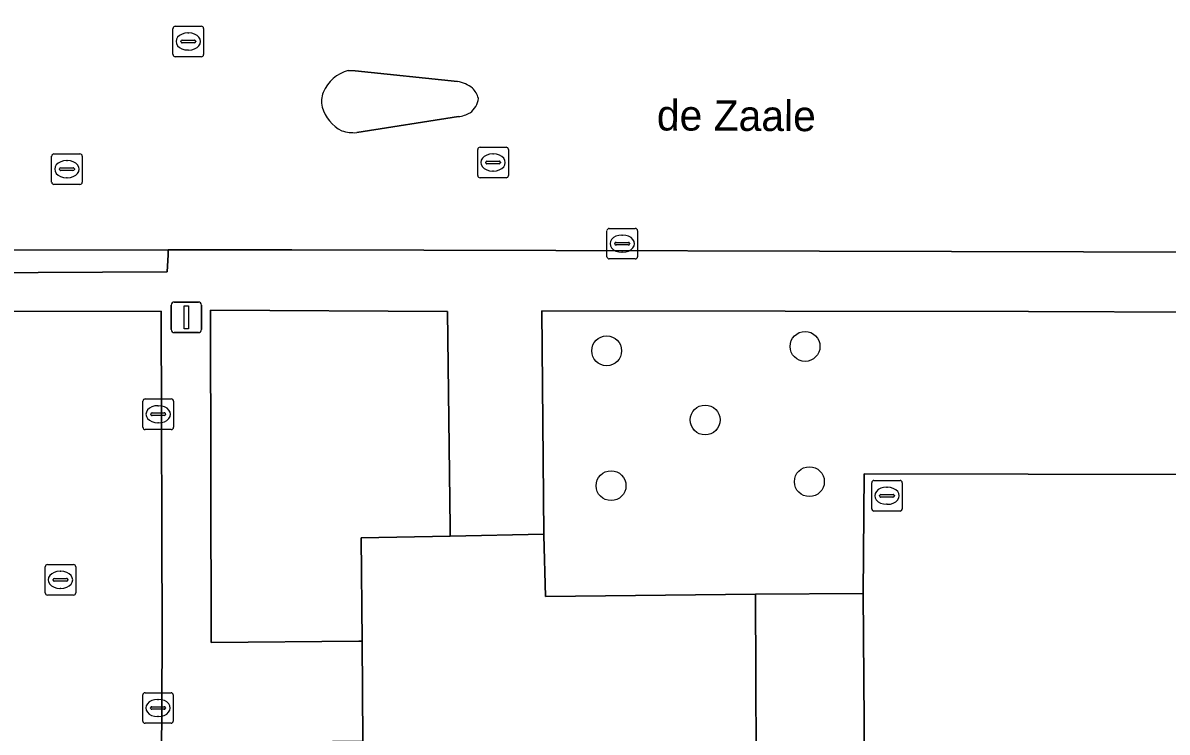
# Model space of a CAD drawing. Extents: x 161477 to 163040, y 383680 to 384871.
# Drawn here: x 161809.61 to 161847.07, y 384356.35 to 384379.58 of the extents above; entities that cross this region are included whole.
import ezdxf

# ---------------------------------------------------------------- set-up
doc = ezdxf.new("R2010")
doc.units = 0
for name, color, linetype in [('IMGEO_Boom', 7, 'Continuous'), ('IMGEO_Groenvoorziening', 7, 'Continuous'), ('IMGEO_Kolk', 7, 'Continuous'), ('IMGEO_Lichtmast', 7, 'Continuous'), ('IMGEO_Openbare_ruimte_label', 7, 'Continuous'), ('IMGEO_Rijbaan_lokaal_open', 7, 'Continuous'), ('IMGEO_Rioolput', 7, 'Continuous'), ('IMGEO_Verkeerseiland_open', 7, 'Continuous'), ('IMGEO_Voetpad_op_trap', 7, 'Continuous'), ('IMGEO_Voetpad_open', 7, 'Continuous')]:
    doc.layers.add(name, color=color, linetype=linetype)

msp = doc.modelspace()

# ---------------------------------------------------------------- linework, layer by layer
at = {"layer": 'IMGEO_Boom'}
for centre in [(161835.213, 384368.986), (161828.719, 384368.843), (161831.942, 384366.577), (161835.355, 384364.556), (161828.862, 384364.424)]:
    msp.add_circle(centre, 0.489, dxfattribs=at)
at = {"layer": 'IMGEO_Groenvoorziening'}
for points in [[(161823.509, 384370.128), (161815.746, 384370.177), (161815.772, 384359.283), (161820.602, 384359.329), (161820.711, 384359.33), (161820.686, 384362.714), (161823.595, 384362.772), (161823.592, 384363.058)], [(161860.901, 384369.01), (161859.337, 384369.912), (161859.393, 384370.069), (161842.531, 384370.13), (161826.596, 384370.149), (161826.665, 384362.833), (161826.665, 384362.807), (161826.719, 384360.791), (161833.591, 384360.874), (161837.12, 384360.892), (161837.147, 384364.815), (161847.882, 384364.794), (161866.104, 384364.813), (161866.116, 384365.577), (161866.118, 384365.909)]]:
    msp.add_lwpolyline(points, close=True, dxfattribs=at)
at = {"layer": 'IMGEO_Kolk'}
for p, q in [((161828.804, 384372.851), (161829.656, 384372.851)), ((161828.729, 384371.925), (161828.729, 384372.777)), ((161829.217, 384372.631), (161829.242, 384372.631)), ((161829.73, 384372.777), (161829.73, 384371.925)), ((161828.988, 384372.345), (161828.988, 384372.357)), ((161829.426, 384372.308), (161829.028, 384372.308)), ((161829.031, 384372.394), (161829.429, 384372.394)), ((161829.472, 384372.357), (161829.472, 384372.345)), ((161829.656, 384371.851), (161828.804, 384371.851)), ((161829.24, 384372.071), (161829.215, 384372.071)), ((161813.613, 384367.264), (161814.465, 384367.264)), ((161813.538, 384366.338), (161813.538, 384367.19)), ((161814.026, 384367.044), (161814.051, 384367.044)), ((161814.539, 384367.19), (161814.539, 384366.338)), ((161813.797, 384366.758), (161813.797, 384366.77)), ((161814.235, 384366.721), (161813.837, 384366.721)), ((161813.84, 384366.807), (161814.238, 384366.807)), ((161814.049, 384366.484), (161814.024, 384366.484)), ((161814.281, 384366.77), (161814.281, 384366.758)), ((161814.465, 384366.264), (161813.613, 384366.264)), ((161837.47, 384364.595), (161838.322, 384364.595)), ((161837.395, 384363.669), (161837.395, 384364.521)), ((161837.883, 384364.375), (161837.908, 384364.375)), ((161838.396, 384364.521), (161838.396, 384363.669)), ((161837.654, 384364.089), (161837.654, 384364.101)), ((161838.092, 384364.052), (161837.694, 384364.052)), ((161837.697, 384364.138), (161838.095, 384364.138)), ((161838.138, 384364.101), (161838.138, 384364.089)), ((161838.322, 384363.595), (161837.47, 384363.595)), ((161837.906, 384363.815), (161837.881, 384363.815)), ((161813.531, 384356.717), (161813.531, 384357.569)), ((161813.606, 384357.643), (161814.458, 384357.643)), ((161814.532, 384357.569), (161814.532, 384356.717)), ((161813.79, 384357.137), (161813.79, 384357.149)), ((161814.228, 384357.1), (161813.83, 384357.1)), ((161813.833, 384357.186), (161814.231, 384357.186)), ((161814.019, 384357.423), (161814.044, 384357.423)), ((161814.274, 384357.149), (161814.274, 384357.137)), ((161814.042, 384356.863), (161814.017, 384356.863)), ((161814.458, 384356.643), (161813.606, 384356.643))]:
    msp.add_line(p, q, dxfattribs=at)
for points in [[(161828.804, 384372.851), (161829.656, 384372.851)], [(161828.729, 384371.925), (161828.729, 384372.777)], [(161829.73, 384372.777), (161829.73, 384371.925)], [(161829.656, 384371.851), (161828.804, 384371.851)], [(161813.613, 384367.264), (161814.465, 384367.264)], [(161813.538, 384366.338), (161813.538, 384367.19)], [(161814.539, 384367.19), (161814.539, 384366.338)], [(161814.465, 384366.264), (161813.613, 384366.264)], [(161837.47, 384364.595), (161838.322, 384364.595)], [(161837.395, 384363.669), (161837.395, 384364.521)], [(161838.396, 384364.521), (161838.396, 384363.669)], [(161838.322, 384363.595), (161837.47, 384363.595)], [(161813.531, 384356.717), (161813.531, 384357.569)], [(161813.606, 384357.643), (161814.458, 384357.643)], [(161814.532, 384357.569), (161814.532, 384356.717)], [(161814.458, 384356.643), (161813.606, 384356.643)]]:
    msp.add_lwpolyline(points, dxfattribs=at)
for centre, radius, start, end in [((161828.806, 384372.775), 0.0765, 91.552, 178.448), ((161828.806, 384372.775), 0.0765, 91.552, 178.448), ((161829.654, 384372.775), 0.0765, 1.552, 88.448), ((161829.654, 384372.775), 0.0765, 1.552, 88.448), ((161829.028, 384372.354), 0.0403, 85.8775, 175.7526), ((161829.025, 384372.344), 0.0366, 178.938, 274.7102), ((161829.429, 384372.351), 0.043, 264.8664, 352.4533), ((161829.433, 384372.356), 0.0386, 1.7309, 96.639), ((161828.806, 384371.927), 0.0765, 181.552, 268.448), ((161828.806, 384371.927), 0.0765, 181.552, 268.448), ((161829.654, 384371.927), 0.0765, 271.552, 358.448), ((161829.654, 384371.927), 0.0765, 271.552, 358.448), ((161813.615, 384367.188), 0.0765, 91.552, 178.448), ((161813.615, 384367.188), 0.0765, 91.552, 178.448), ((161814.463, 384367.188), 0.0765, 1.552, 88.448), ((161814.463, 384367.188), 0.0765, 1.552, 88.448), ((161813.837, 384366.767), 0.0403, 85.8775, 175.7526), ((161813.834, 384366.757), 0.0366, 178.938, 274.7102), ((161814.238, 384366.764), 0.043, 264.8664, 352.4533), ((161814.242, 384366.769), 0.0386, 1.7309, 96.639), ((161813.615, 384366.34), 0.0765, 181.552, 268.448), ((161813.615, 384366.34), 0.0765, 181.552, 268.448), ((161814.463, 384366.34), 0.0765, 271.552, 358.448), ((161814.463, 384366.34), 0.0765, 271.552, 358.448), ((161837.472, 384364.519), 0.0765, 91.552, 178.448), ((161837.472, 384364.519), 0.0765, 91.552, 178.448), ((161838.32, 384364.519), 0.0765, 1.552, 88.448), ((161838.32, 384364.519), 0.0765, 1.552, 88.448), ((161837.694, 384364.098), 0.0403, 85.8775, 175.7526), ((161837.691, 384364.088), 0.0366, 178.938, 274.7102), ((161838.095, 384364.095), 0.043, 264.8664, 352.4533), ((161838.099, 384364.1), 0.0386, 1.7309, 96.639), ((161837.472, 384363.671), 0.0765, 181.552, 268.448), ((161837.472, 384363.671), 0.0765, 181.552, 268.448), ((161838.32, 384363.671), 0.0765, 271.552, 358.448), ((161838.32, 384363.671), 0.0765, 271.552, 358.448), ((161813.608, 384357.567), 0.0765, 91.552, 178.448), ((161813.608, 384357.567), 0.0765, 91.552, 178.448), ((161814.456, 384357.567), 0.0765, 1.552, 88.448), ((161814.456, 384357.567), 0.0765, 1.552, 88.448), ((161813.83, 384357.146), 0.0403, 85.8775, 175.7526), ((161813.827, 384357.136), 0.0366, 178.938, 274.7102), ((161814.231, 384357.143), 0.043, 264.8664, 352.4533), ((161814.235, 384357.148), 0.0386, 1.7309, 96.639), ((161813.608, 384356.719), 0.0765, 181.552, 268.448), ((161813.608, 384356.719), 0.0765, 181.552, 268.448), ((161814.456, 384356.719), 0.0765, 271.552, 358.448), ((161814.456, 384356.719), 0.0765, 271.552, 358.448)]:
    msp.add_arc(centre, radius, start, end, dxfattribs=at)
for centre, major_axis, ratio, start_param, end_param in [((161829.216, 384372.351), (-0.387, 0.002), 0.722429, 4.712389, 7.853982), ((161829.241, 384372.351), (-0.39, 0.002), 0.717154, 1.570796, 4.712389), ((161814.025, 384366.764), (-0.387, 0.002), 0.722429, 4.712389, 7.853982), ((161814.05, 384366.764), (-0.39, 0.002), 0.717154, 1.570796, 4.712389), ((161837.882, 384364.095), (-0.387, 0.002), 0.722429, 4.712389, 7.853982), ((161837.907, 384364.095), (-0.39, 0.002), 0.717154, 1.570796, 4.712389), ((161814.018, 384357.143), (-0.387, 0.002), 0.722429, 4.712389, 7.853982), ((161814.043, 384357.143), (-0.39, 0.002), 0.717154, 1.570796, 4.712389)]:
    msp.add_ellipse(centre, major_axis=major_axis, ratio=ratio, start_param=start_param, end_param=end_param, dxfattribs=at)
at = {"layer": 'IMGEO_Lichtmast'}
for p, q in [((161814.464, 384369.539), (161814.464, 384370.339)), ((161814.464, 384370.339), (161814.464, 384369.539)), ((161814.564, 384370.439), (161815.354, 384370.439)), ((161815.354, 384370.439), (161814.564, 384370.439)), ((161815.454, 384370.339), (161815.454, 384369.539)), ((161815.454, 384369.539), (161815.454, 384370.339)), ((161815.354, 384369.439), (161814.564, 384369.439)), ((161814.564, 384369.439), (161815.354, 384369.439))]:
    msp.add_line(p, q, dxfattribs=at)
msp.add_lwpolyline([(161814.884, 384370.314), (161815.034, 384370.314), (161815.034, 384369.564), (161814.884, 384369.564), (161814.884, 384370.314)], dxfattribs=at)
for centre, start, end in [((161814.564, 384370.339), 90, 180), ((161814.564, 384370.339), 90, 180), ((161815.354, 384370.339), 0, 90), ((161815.354, 384370.339), 360, 90), ((161814.564, 384369.539), 180, 270), ((161814.564, 384369.539), 180, 270), ((161815.354, 384369.539), 270, 0), ((161815.354, 384369.539), 270, 0)]:
    msp.add_arc(centre, 0.1, start, end, dxfattribs=at)
at = {"layer": 'IMGEO_Rijbaan_lokaal_open'}
for points in [[(161807.986, 384389.164), (161807.967, 384386.159), (161807.953, 384382.43), (161807.983, 384372.238), (161807.983, 384372.135), (161814.368, 384372.145), (161818.41, 384372.152), (161844.332, 384372.085), (161861.126, 384372.071), (161865.791, 384372.068), (161865.845, 384382.002), (161864.089, 384382.01), (161859.71, 384382.026), (161858.115, 384382.027), (161834.388, 384382.049), (161828.143, 384382.055), (161827.142, 384382.092)], [(161820.257, 384378.027), (161820.487, 384378.015), (161823.835, 384377.663)], [(161823.868, 384376.515), (161820.537, 384375.987)], [(161814.06, 384323.352), (161814.035, 384329.719), (161814.102, 384340.861), (161814.121, 384351.376), (161814.162, 384359.441), (161814.131, 384370.138), (161807.989, 384370.133), (161807.949, 384361.27), (161807.917, 384350.655), (161807.908, 384348.04), (161807.911, 384343.752), (161807.912, 384342.77), (161807.864, 384334.408), (161807.877, 384324.354)]]:
    msp.add_lwpolyline(points, dxfattribs=at)
for centre, radius, start, end in [((161820.613, 384376.806), 1.272, 106.2566, 156.888), ((161823.687, 384376.676), 0.998, 50.3941, 81.4633), ((161823.804, 384376.919), 0.739, 14.8896, 45.3685), ((161820.099, 384377.02), 0.716, 156.4919, 195.6095), ((161823.868, 384377.17), 0.653, 305.2923, 354.6184), ((161820.613, 384377.16), 1.249, 195.4874, 243.0755), ((161823.753, 384377.513), 1.005, 276.5601, 299.3038), ((161820.48, 384377.543), 1.557, 253.9011, 272.1085)]:
    msp.add_arc(centre, radius, start, end, dxfattribs=at)
at = {"layer": 'IMGEO_Rioolput'}
for p, q in [((161814.522, 384378.548), (161814.522, 384379.4)), ((161814.597, 384379.474), (161815.449, 384379.474)), ((161815.01, 384379.254), (161815.035, 384379.254)), ((161815.523, 384379.4), (161815.523, 384378.548)), ((161814.781, 384378.968), (161814.781, 384378.98)), ((161815.219, 384378.931), (161814.821, 384378.931)), ((161814.824, 384379.017), (161815.222, 384379.017)), ((161815.265, 384378.98), (161815.265, 384378.968)), ((161815.449, 384378.474), (161814.597, 384378.474)), ((161815.033, 384378.694), (161815.008, 384378.694)), ((161824.574, 384375.51), (161825.426, 384375.51)), ((161810.55, 384374.365), (161810.55, 384375.217)), ((161810.625, 384375.291), (161811.477, 384375.291)), ((161811.551, 384375.217), (161811.551, 384374.365)), ((161824.499, 384374.584), (161824.499, 384375.436)), ((161824.987, 384375.29), (161825.012, 384375.29)), ((161825.5, 384375.436), (161825.5, 384374.584)), ((161810.809, 384374.785), (161810.809, 384374.797)), ((161811.247, 384374.748), (161810.849, 384374.748)), ((161810.852, 384374.834), (161811.25, 384374.834)), ((161811.038, 384375.071), (161811.063, 384375.071)), ((161811.293, 384374.797), (161811.293, 384374.785)), ((161824.758, 384375.004), (161824.758, 384375.016)), ((161825.196, 384374.967), (161824.798, 384374.967)), ((161824.801, 384375.053), (161825.199, 384375.053)), ((161825.01, 384374.73), (161824.985, 384374.73)), ((161825.242, 384375.016), (161825.242, 384375.004)), ((161811.061, 384374.511), (161811.036, 384374.511)), ((161825.426, 384374.51), (161824.574, 384374.51)), ((161811.477, 384374.291), (161810.625, 384374.291)), ((161810.337, 384360.915), (161810.337, 384361.767)), ((161810.412, 384361.841), (161811.264, 384361.841)), ((161810.825, 384361.621), (161810.85, 384361.621)), ((161811.338, 384361.767), (161811.338, 384360.915)), ((161810.596, 384361.335), (161810.596, 384361.347)), ((161811.034, 384361.298), (161810.636, 384361.298)), ((161810.639, 384361.384), (161811.037, 384361.384)), ((161811.08, 384361.347), (161811.08, 384361.335)), ((161811.264, 384360.841), (161810.412, 384360.841)), ((161810.848, 384361.061), (161810.823, 384361.061))]:
    msp.add_line(p, q, dxfattribs=at)
for points in [[(161814.522, 384378.548), (161814.522, 384379.4)], [(161814.597, 384379.474), (161815.449, 384379.474)], [(161815.523, 384379.4), (161815.523, 384378.548)], [(161815.449, 384378.474), (161814.597, 384378.474)], [(161824.574, 384375.51), (161825.426, 384375.51)], [(161810.55, 384374.365), (161810.55, 384375.217)], [(161810.625, 384375.291), (161811.477, 384375.291)], [(161811.551, 384375.217), (161811.551, 384374.365)], [(161824.499, 384374.584), (161824.499, 384375.436)], [(161825.5, 384375.436), (161825.5, 384374.584)], [(161825.426, 384374.51), (161824.574, 384374.51)], [(161811.477, 384374.291), (161810.625, 384374.291)], [(161810.337, 384360.915), (161810.337, 384361.767)], [(161810.412, 384361.841), (161811.264, 384361.841)], [(161811.338, 384361.767), (161811.338, 384360.915)], [(161811.264, 384360.841), (161810.412, 384360.841)]]:
    msp.add_lwpolyline(points, dxfattribs=at)
for centre, radius, start, end in [((161814.599, 384379.398), 0.0765, 91.552, 178.448), ((161814.599, 384379.398), 0.0765, 91.552, 178.448), ((161815.447, 384379.398), 0.0765, 1.552, 88.448), ((161815.447, 384379.398), 0.0765, 1.552, 88.448), ((161814.821, 384378.977), 0.0403, 85.8775, 175.7526), ((161814.818, 384378.967), 0.0366, 178.938, 274.7102), ((161815.222, 384378.974), 0.043, 264.8664, 352.4533), ((161815.226, 384378.979), 0.0386, 1.7309, 96.639), ((161814.599, 384378.55), 0.0765, 181.552, 268.448), ((161814.599, 384378.55), 0.0765, 181.552, 268.448), ((161815.447, 384378.55), 0.0765, 271.552, 358.448), ((161815.447, 384378.55), 0.0765, 271.552, 358.448), ((161824.576, 384375.434), 0.0765, 91.552, 178.448), ((161824.576, 384375.434), 0.0765, 91.552, 178.448), ((161825.424, 384375.434), 0.0765, 1.552, 88.448), ((161825.424, 384375.434), 0.0765, 1.552, 88.448), ((161810.627, 384375.215), 0.0765, 91.552, 178.448), ((161810.627, 384375.215), 0.0765, 91.552, 178.448), ((161811.475, 384375.215), 0.0765, 1.552, 88.448), ((161811.475, 384375.215), 0.0765, 1.552, 88.448), ((161810.849, 384374.794), 0.0403, 85.8775, 175.7526), ((161810.846, 384374.784), 0.0366, 178.938, 274.7102), ((161811.25, 384374.791), 0.043, 264.8664, 352.4533), ((161811.254, 384374.796), 0.0386, 1.7309, 96.639), ((161824.798, 384375.013), 0.0403, 85.8775, 175.7526), ((161824.795, 384375.003), 0.0366, 178.938, 274.7102), ((161825.199, 384375.01), 0.043, 264.8664, 352.4533), ((161825.203, 384375.015), 0.0386, 1.7309, 96.639), ((161810.627, 384374.367), 0.0765, 181.552, 268.448), ((161810.627, 384374.367), 0.0765, 181.552, 268.448), ((161811.475, 384374.367), 0.0765, 271.552, 358.448), ((161811.475, 384374.367), 0.0765, 271.552, 358.448), ((161824.576, 384374.586), 0.0765, 181.552, 268.448), ((161824.576, 384374.586), 0.0765, 181.552, 268.448), ((161825.424, 384374.586), 0.0765, 271.552, 358.448), ((161825.424, 384374.586), 0.0765, 271.552, 358.448), ((161810.414, 384361.765), 0.0765, 91.552, 178.448), ((161810.414, 384361.765), 0.0765, 91.552, 178.448), ((161811.262, 384361.765), 0.0765, 1.552, 88.448), ((161811.262, 384361.765), 0.0765, 1.552, 88.448), ((161810.636, 384361.344), 0.0403, 85.8775, 175.7526), ((161810.633, 384361.334), 0.0366, 178.938, 274.7102), ((161811.037, 384361.341), 0.043, 264.8664, 352.4533), ((161811.041, 384361.346), 0.0386, 1.7309, 96.639), ((161810.414, 384360.917), 0.0765, 181.552, 268.448), ((161810.414, 384360.917), 0.0765, 181.552, 268.448), ((161811.262, 384360.917), 0.0765, 271.552, 358.448), ((161811.262, 384360.917), 0.0765, 271.552, 358.448)]:
    msp.add_arc(centre, radius, start, end, dxfattribs=at)
for centre, major_axis, ratio, start_param, end_param in [((161815.009, 384378.974), (-0.387, 0.002), 0.722429, 4.712389, 7.853982), ((161815.034, 384378.974), (-0.39, 0.002), 0.717154, 1.570796, 4.712389), ((161824.986, 384375.01), (-0.387, 0.002), 0.722429, 4.712389, 7.853982), ((161825.011, 384375.01), (-0.39, 0.002), 0.717154, 1.570796, 4.712389), ((161811.037, 384374.791), (-0.387, 0.002), 0.722429, 4.712389, 7.853982), ((161811.062, 384374.791), (-0.39, 0.002), 0.717154, 1.570796, 4.712389), ((161810.824, 384361.341), (-0.387, 0.002), 0.722429, 4.712389, 7.853982), ((161810.849, 384361.341), (-0.39, 0.002), 0.717154, 1.570796, 4.712389)]:
    msp.add_ellipse(centre, major_axis=major_axis, ratio=ratio, start_param=start_param, end_param=end_param, dxfattribs=at)
at = {"layer": 'IMGEO_Verkeerseiland_open'}
for points in [[(161823.835, 384377.663), (161820.487, 384378.015), (161820.257, 384378.027)], [(161820.537, 384375.987), (161823.868, 384376.515)]]:
    msp.add_lwpolyline(points, dxfattribs=at)
for centre, radius, start, end in [((161820.613, 384376.806), 1.272, 106.2566, 156.888), ((161823.687, 384376.676), 0.998, 50.3941, 81.4633), ((161823.804, 384376.919), 0.739, 14.8896, 45.3685), ((161820.099, 384377.02), 0.716, 156.4919, 195.6095), ((161823.868, 384377.17), 0.653, 305.2923, 354.6184), ((161820.613, 384377.16), 1.249, 195.4874, 243.0755), ((161823.753, 384377.513), 1.005, 276.5601, 299.3038), ((161820.48, 384377.543), 1.557, 253.9011, 272.1085)]:
    msp.add_arc(centre, radius, start, end, dxfattribs=at)
at = {"layer": 'IMGEO_Voetpad_op_trap'}
msp.add_lwpolyline([(161837.12, 384360.892), (161833.591, 384360.874), (161833.626, 384352.84), (161828.61, 384352.789), (161828.628, 384350.278), (161828.852, 384350.283), (161838.993, 384350.379), (161839.129, 384350.38), (161839.159, 384353.911), (161837.171, 384353.896)], close=True, dxfattribs=at)
at = {"layer": 'IMGEO_Voetpad_open'}
for points in [[(161861.126, 384372.071), (161844.332, 384372.085), (161818.41, 384372.152), (161814.368, 384372.145), (161814.361, 384371.982), (161814.335, 384371.427), (161807.978, 384371.397)], [(161807.989, 384370.133), (161814.131, 384370.138), (161814.162, 384359.441), (161814.121, 384351.376), (161814.102, 384340.861), (161814.035, 384329.719), (161815.738, 384329.725), (161815.749, 384340.907), (161815.769, 384351.143), (161815.773, 384356.015), (161820.736, 384356.063), (161820.711, 384359.33), (161820.602, 384359.329), (161815.772, 384359.283), (161815.746, 384370.177), (161823.509, 384370.128), (161823.592, 384363.058), (161823.595, 384362.772), (161826.665, 384362.833), (161826.596, 384370.149), (161842.531, 384370.13), (161859.393, 384370.069)]]:
    msp.add_lwpolyline(points, dxfattribs=at)
for points in [[(161814.361, 384371.982), (161814.368, 384372.145), (161807.983, 384372.135), (161807.978, 384371.397), (161814.335, 384371.427)], [(161847.888, 384361.652), (161847.888, 384361.969), (161847.463, 384361.963), (161847.448, 384363.203), (161847.914, 384363.209), (161847.882, 384364.794), (161837.147, 384364.815), (161837.12, 384360.892), (161837.171, 384353.896), (161839.159, 384353.911), (161847.908, 384353.974)], [(161833.591, 384360.874), (161826.719, 384360.791), (161826.665, 384362.807), (161826.665, 384362.833), (161823.595, 384362.772), (161820.686, 384362.714), (161820.711, 384359.33), (161820.736, 384356.063), (161820.762, 384352.722), (161823.67, 384352.743), (161828.425, 384352.791), (161828.61, 384352.789), (161833.626, 384352.84)]]:
    msp.add_lwpolyline(points, close=True, dxfattribs=at)

# ---------------------------------------------------------------- texts
at = {"layer": 'IMGEO_Openbare_ruimte_label'}
msp.add_text('de Zaale', height=1, rotation=359.7135, dxfattribs=at).set_placement((161830.361, 384376.06))

doc.saveas('drawing.dxf')
